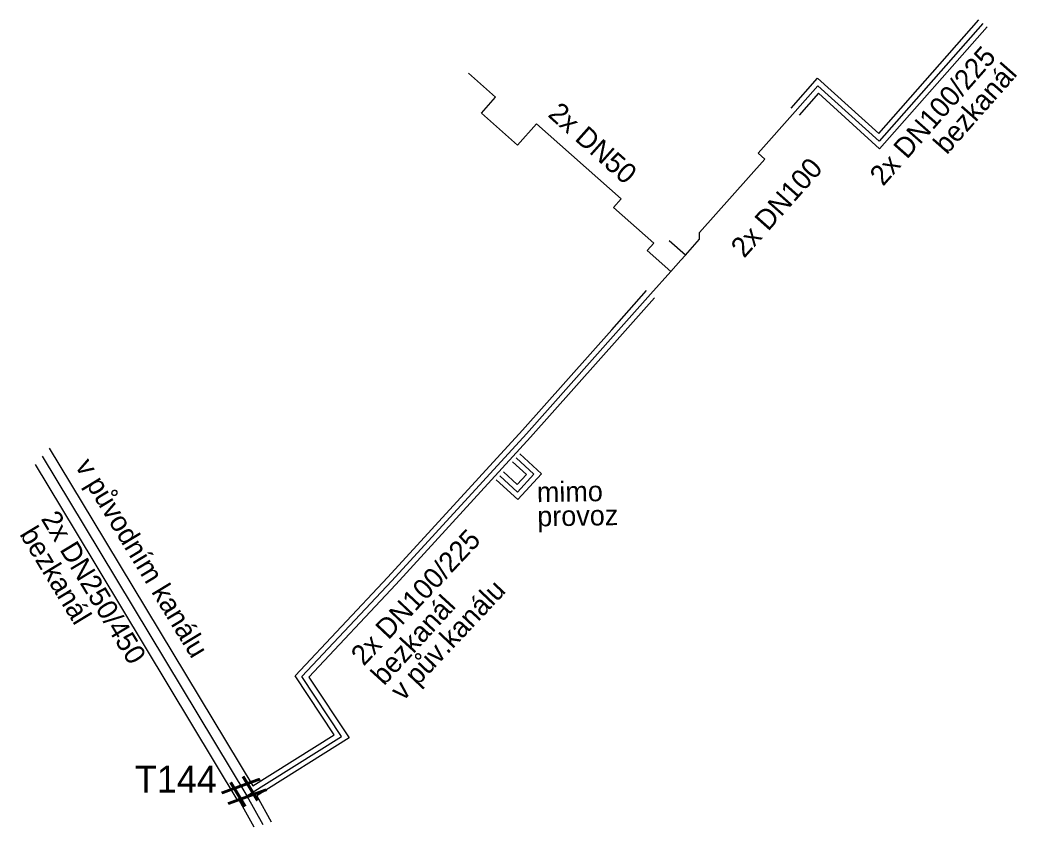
# Model space of a CAD drawing. Extents: x -598419.6 to -598345.5, y -1159752.4 to -1159692.4.
import ezdxf

# ---------------------------------------------------------------- set-up
doc = ezdxf.new("R2010")
doc.units = 0
for name, color, linetype in [('Horkovod - trasa - okraj', 7, 'Continuous'), ('Horkovod - trasa popis', 7, 'Continuous'), ('Horkovod - trasa popis 2', 7, 'Continuous'), ('Horkovod - trasa popis 3', 7, 'Continuous'), ('Osa trasy horkovodu', 7, 'Continuous'), ('Osa trasy parovodu', 7, 'Continuous'), ('označení', 7, 'Continuous'), ('Parovod - trasa - okraj', 7, 'Continuous'), ('Parovod - trasa popis 2', 7, 'Continuous'), ('Šachta trasy horkovodu', 7, 'Continuous')]:
    doc.layers.add(name, color=color, linetype=linetype)

msp = doc.modelspace()

# ---------------------------------------------------------------- linework, layer by layer
at = {"layer": 'Horkovod - trasa - okraj'}
for points in [[(-598362.257, -1159698.979), (-598360.29, -1159696.748), (-598355.741, -1159700.864), (-598348.299, -1159692.428)], [(-598347.685, -1159692.941), (-598355.677, -1159702.001), (-598360.226, -1159697.884), (-598361.657, -1159699.509)], [(-598402.278, -1159749.378), (-598396.226, -1159745.576), (-598399.13, -1159741.199), (-598392.228, -1159733.867), (-598382.227, -1159722.925), (-598375.577, -1159715.458), (-598372.999, -1159712.557)], [(-598372.401, -1159713.088), (-598374.98, -1159715.99), (-598381.633, -1159723.461), (-598391.641, -1159734.411), (-598398.113, -1159741.286), (-598395.106, -1159745.817), (-598401.962, -1159750.124)], [(-598417.408, -1159724.269), (-598414.169, -1159729.649), (-598402.278, -1159749.378)], [(-598403.349, -1159750.506), (-598415.454, -1159730.423), (-598418.433, -1159725.474)], [(-598402.168, -1159752.439), (-598403.276, -1159750.434)], [(-598401.962, -1159750.124), (-598400.894, -1159752.057)]]:
    msp.add_lwpolyline(points, dxfattribs=at)
at = {"layer": 'Osa trasy horkovodu'}
for p, q in [((-598370.115, -1159709.916), (-598371.311, -1159708.853)), ((-598372.7, -1159712.823), (-598371.192, -1159711.126))]:
    msp.add_line(p, q, dxfattribs=at)
for points in [[(-598347.992, -1159692.684), (-598355.709, -1159701.433), (-598360.258, -1159697.316), (-598361.957, -1159699.244)], [(-598371.192, -1159711.126), (-598372.948, -1159709.565), (-598372.464, -1159709.021), (-598375.453, -1159706.363), (-598374.895, -1159705.735), (-598381.171, -1159700.153), (-598382.587, -1159701.744), (-598385.277, -1159699.352), (-598384.227, -1159698.171), (-598386.245, -1159696.377)], [(-598370.115, -1159709.916), (-598369.052, -1159708.72), (-598369.052, -1159708.227), (-598364.214, -1159702.788), (-598364.714, -1159702.344), (-598361.957, -1159699.244)], [(-598371.192, -1159711.126), (-598370.447, -1159710.289), (-598370.115, -1159709.916)], [(-598402.707, -1159750.119), (-598395.666, -1159745.696), (-598398.622, -1159741.242), (-598391.934, -1159734.139), (-598381.93, -1159723.193), (-598375.279, -1159715.724), (-598372.7, -1159712.823)], [(-598417.92, -1159724.872), (-598414.812, -1159730.036), (-598402.707, -1159750.119)], [(-598402.707, -1159750.119), (-598401.531, -1159752.248)]]:
    msp.add_lwpolyline(points, dxfattribs=at)
at = {"layer": 'Osa trasy parovodu'}
msp.add_lwpolyline([(-598383.913, -1159726.317), (-598382.584, -1159727.531), (-598381.37, -1159726.202), (-598382.699, -1159724.988)], dxfattribs=at)
at = {"layer": 'Parovod - trasa - okraj'}
for points in [[(-598382.429, -1159724.693), (-598380.805, -1159726.176), (-598382.558, -1159728.096), (-598384.183, -1159726.612)], [(-598383.644, -1159726.021), (-598382.61, -1159726.966), (-598381.935, -1159726.228), (-598382.969, -1159725.284)]]:
    msp.add_lwpolyline(points, dxfattribs=at)

# ---------------------------------------------------------------- texts
at = {"layer": 'Horkovod - trasa popis'}
for s, rotation, p in [('2x DN100/225', 48.58573, (-598355.418, -1159704.844)), ('2x DN50', 318.35192, (-598380.409, -1159699.546)), ('2x DN100', 48.35192, (-598365.747, -1159710.194)), ('2x DN250/450', 301.24728, (-598418.056, -1159729.514)), ('2x DN100/225', 46.72763, (-598394.025, -1159740.519))]:
    msp.add_text(s, height=1.5, rotation=rotation, dxfattribs=at).set_placement(p)
at = {"layer": 'Horkovod - trasa popis 2'}
for rotation, p in [(48.58573, (-598350.681, -1159702.499)), (301.24728, (-598419.646, -1159730.662)), (47.57516, (-598392.514, -1159741.982))]:
    msp.add_text('bezkanál', height=1.5, rotation=rotation, dxfattribs=at).set_placement(p)
at = {"layer": 'Horkovod - trasa popis 3'}
for s, rotation, p in [('v původním kanálu', 301.24728, (-598415.512, -1159725.606)), ('v pův.kanálu', 46.72763, (-598391.1, -1159743.13))]:
    msp.add_text(s, height=1.5, rotation=rotation, dxfattribs=at).set_placement(p)
at = {"layer": 'označení'}
msp.add_text('T144', height=2, dxfattribs=at).set_placement((-598411.036, -1159749.879))
at = {"layer": 'Parovod - trasa popis 2'}
for s, p in [('mimo', (-598381.142, -1159728.286)), ('provoz', (-598381.112, -1159730.086))]:
    msp.add_text(s, height=1.5, rotation=0.94912, dxfattribs=at).set_placement(p)
at = {"layer": 'Šachta trasy horkovodu'}
msp.add_text('#', height=3, rotation=301.07807, dxfattribs=at).set_placement((-598404.768, -1159749.606))

doc.saveas('drawing.dxf')
